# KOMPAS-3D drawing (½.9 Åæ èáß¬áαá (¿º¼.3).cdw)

Views: Вид 1, Вид 2
Referenced files in C:\Program Files\ASCON\KOMPAS-3D V10\Sys\: SPDS.lcs
Referenced files: План ПС Сазоново.cdw
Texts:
  Ирина
  Текст на чертеже
  Размерные надписи
  Шероховатость
  Линия-выноска #1
  Линия-выноска #2
  Линия-выноска #3
  Отклонения формы и база
  Заголовок таблицы
  Ячейка таблицы
  Стрелка вида
  Обозначение изменения
  Фигурная скобка
  Номер узла
  Марка координационной оси
  VRCB
  Выносная надпись
  Обозначение узла
  Марка/позиционное обозначение с линией-выноской
  Марка/позиционное обозначение на линии
  Марка/позиционное обозначение без линии-выноски
  Normal
  Лит-Масса-Масштаб
  Материал-Предприятие
  Title Specification
  Body Specification ( left align )
  Body Specificaton ( centered )
  Без имени
  heading 1
  Знак Знак Знак Знак Знак Знак
  Verdana
  Body Text
  MS Sans Serif
  Txt
  Simplex
  TXT
  Обычный
  Термин
  Список определений
  Адрес
  Цитаты
  Форматированный
  Courier New
  Z-конец формы
  Z-начало формы
  Additional DXF text style 0
  Абзац Знак
  Body Text 3
  Title
  ТекстШаг1
  Шрифт 2.5
  Заголовки
  txt
  heading 2
  AGOpus
  footer
  Денис
  RUSTXT
  Обычный (веб)
  ООббыыччнныыйй
  Definition Term
  Definition List
  Address
  Blockquote
  Preformatted
  z-Bottom of Form
  z-Top of Form
  header
  NormalParagraphStyle
  ссылки
  Подпись в квадратике
  табл
  цепи
  Маркировка
  клеммы, контакты
  тексты табл
  Тексты. 3,2
  ЗОНА_привяз
  текст переноса
  ТТееррммиинн
  ССппииссоокк ооппррееддееллеенниийй
  ААддрреесс
  ЦЦииттааттыы
  ФФооррммааттиирроовваанннныыйй
  Z-ккооннеецц ффооррммыы
  Z-ннааччааллоо ффооррммыы
  GOST 2.304 type A
  rustxt
  heading 8
  heading 3
  heading 6
  heading 7
  russ
  heading 4
  heading 5
  heading 9
  HeliosLight
  Pa3
  Pa1
  Три с половиной
  style2
  Table Contents
  Table Heading
  ГОСТ_МНЕ
  ESK - Обозначение
  маркировка
  ISOCP
  ROMANS
  SIMPLEX
  Текст 3,5
  Tahoma
  CNBNDG+TimesNewRoman
  Subtitle
  FR5
  romanc
  eskd1
  Pa15
  Pa18
  Аппараты
  подписи
  Состав чартежа
  ячейка табл.
  Ссылки
  Пояснения
  Клеммник текст
  CM12
  romans
  gif
  Пояснения 2
  текст табл
  ISOCPEUR
  CC С?т?и?л?ь? П?о? ц?е?н?т?р?у?
  SignaColumn-Light
  Cambria
  Normal (Web)
  Подписи
  Ошиновка
  кабельные конструкции
  Примечания:
  1. Для нужд строительства (размещение задействованного в строительстве персонала, обеспечение
  электроэнергией) использовать временные мобильные инвентарные здания;
  2. При выполнении всех строительно-монтажных работ на площадке необходимо руководствоваться
  требованиями СНиП 12-03-2001 "Безопасность труда в строительстве. Общие требования",
  СНиП 12-04-2002 "Безопасность труда в строительстве. Строительное производство", а также
  ПОТ-РМ-016-2001/РД 153-34.0-03.150-00 "Межотраслевые правила по охране труда (правила
  безопасности) при эксплуатации электроустановок";
  3. Наружное освещение строительной площадки осуществляется за счет существующего освещения;
  4. Под временные сооружения (поз. II, III и IV) устраивается площадка из дорожных плит ПД 60-20 на
  щебеночном основании толщиной 15см;
  5. На период строительства для электроснабжения временных зданий и сооружений использовать ди-
  зельную электростанцию. Прокладку  кабеля от дизельной электростанции до вагончиков выполнить
  в воздушном исполнении в гофрированной трубе диаметром 30 мм, на вагончиках кабель закрепить
  скобами. Щиток временного электроснабжения навесить на стенку вагона-дома для отдыха рабочих;
  6. При выполнении монтажных работ использовать инвентарные лестницы и леса;
  7. Тонкой линией изображено существующее оборудование, замена которого проектом не предусматри-
  вается, утолщенной - вновь устанавливаемое оборудование.
  8. Условные обозначения см. 16/01-ПОС,л.1.
  9. Демонтировать ограждение на время реконструкции.
  10. Грузовысотные характеристики КМУ ИНМАН ИМ-150 см. 16/01-ПОС,л.7.
  Экспликация зданий и сооружений
  Номер
  на плане
  Постоянные здания и сооружения
  ОПУ
  Существующее
  ЗРУ-10 кВ
  Трансформатор 1Т, маслоприемник
  Существующий
  Трансформатор 2Т, маслоприемник
  Временные здания и сооружения
  III
  Вагон-дом для кратковременного отдых рабочих
  Уборная
  Дизельная электростанция
  Контейнеры для ТБО (0,75м 3 ) и жидких хоз.-быт.стоков(1м 3 )
  «Екатерина» 9,0х3,0
  Туалетная кабина "Люкс"
  ОАО ПКТИпромстрой
  КМУ ИНМАН ИМ-150
  POLYLINE_STYLE_0.25_RGB_128_64_0
  POLYLINE_STYLE_0.18_RGB_0_0_0
  POLYLINE_STYLE_0.20_RGB_0_0_0
  POLYLINE_STYLE_0.18_RGB_0_80_80
  Стили документа
  Бортовой автомобиль КамАЗ 43114-027-02
  АТ ППР#010#0104
  Перезавод ВЛ на ПС Тюмень. Реконструкция устройств
  РЗ и ПА на обратных концах отходящих ВЛ,
  ВОЛС Тюменского ТПО
  Политова
  Разраб.
  Микрюков
  Строительный генеральный план
  ПС 110/10 кВ Каскара
  Ведомость эскизного проекта
  Нов.
  ГИП
  Матвеев
  Ромин
Dimensions and other numbers on the sheet: 16/01-ПОС; 7; 2,5; 1,8; 2.5; 3,2_; 3.5; 3,2; 2,5 (контакты, клеммы); 3,2 (надписи); 3,2 (Зоны); 5; 2,5_01; 2,5_3; 3,5_01; 3,5_tabl; 5_заголовок; 2,3_; 3,2_зона не привяз; 3,5; 3.2 маркировка; 3,2 элементы; 3,2 линия; 3,2 таблица; 2,5 грязносинь; 2.5 курсив; 2.5_Э5_надписи; 2.5_Э5_ссылки; 2.5_кабель; 3.2; 2.5 надписи; 3 и 5; 5,0_белый_подчёркнутый; 3.2 фиол; 3.2 (текст); 1; 2; 3; 4; 10,6; 05.14; 9; 253-14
